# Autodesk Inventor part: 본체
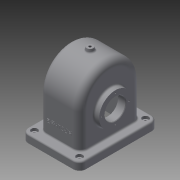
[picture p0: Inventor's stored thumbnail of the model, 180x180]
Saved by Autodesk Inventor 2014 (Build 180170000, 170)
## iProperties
Created: 2016-10
Part Number: 본체
Material: 일반
Document SubType Name: Modeling
Designer: USER
Density: 1 g/cm^3
Appearance: 기본값
Author: USER
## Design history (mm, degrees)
sketch "스케치1"
  geometry: L1 (-58, -65)-(-58, 0); L2 (58, 0)-(58, -65); L3 (58, -65)-(-58, -65); A1 r 58 centre (0, 0) between (58, 0) and (-58, 0); 1 further point
  constraints: 6 end point, 2 point on circle, 2 tangent, 1 centre point, 1 coincident, 1 parallel, 1 perpendicular, 1 vertical
  dimensions: "d0" = 65 distance from line of L3 point (0, 0); "d1" = 58 radius of A1; "d2" = 123 dimension on A1 L3
extrude "돌출1" new body sketch "스케치1" stored distance "d3" = 77; taper "d4" = 0 deg
node "작업 평면1"
sketch "스케치2"
  geometry: L1 (55, -75)-(-55, -75); L2 (-55, -75)-(-55, 75); L3 (-55, 75)-(55, 75); L4 (55, 75)-(55, -75); L5 (55, -75)-(-55, 75); L6 (-55, -75)-(55, 75); 1 further point
  constraints: 12 end point, 2 midpoint, 2 parallel, 1 horizontal, 1 perpendicular
  dimensions: "d6" = 110 distance of L2.end L3.end; "d7" = 150 distance of L1.end L2.end
extrude "돌출2" join sketch "스케치2" distance "d8" = 15; taper "d9" = 0 deg
sketch "스케치3"
  geometry: L1 (-58, -65)-(-58, 0) reference; L2 (-58, -65)-(-58, 0) reference; L3 (58, 0)-(58, -65) reference; L4 (58, -65)-(-58, -65) reference; L5 (52, -80)-(52, 0); L6 (-52, 0)-(-52, -80); L7 (-75, -80)-(75, -80) reference; L8 (-75, -80)-(-75, -65) reference; L9 (75, -65)-(-75, -65) reference; L10 (75, -80)-(75, -65) reference; A1 r 58 centre (0, 0) between (58, 0) and (-58, 0) reference; A2 r 58 centre (0, 0) between (58, 0) and (-58, 0) reference; A3 r 52 centre (0, 0) between (52, 0) and (-52, 0); 1 further point
  constraints: 4 end point, 2 point on circle, 2 point on line, 1 centre point
  dimensions: "d10" = 6 radial gap between concentric circles of A1 A3; "d11" = 6 distance between parallel lines of L1 L6; "d12" = 6 distance between parallel lines of L3 L5
extrude "돌출3" cut sketch "스케치3" stored distance "d13" = 67; taper "d14" = 0 deg
sketch "스케치4"
  geometry: L1 (80, 75)-(80, -75) reference; C1 r 31 at (15, 0); 1 further point
  constraints: 1 centre point, 1 horizontal alignment
  dimensions: "d15" = 62 diameter of C1; "d16" = 65 distance from line of L1 C1.centre
extrude "돌출4" join sketch "스케치4" distance "d17" = 10; taper "d18" = 0 deg
sketch "스케치5"
  geometry: L1 (-80, -75)-(-80, 75) reference; C1 r 37.5 at (-15, 0); 1 further point
  constraints: 1 centre point, 1 horizontal alignment
  dimensions: "d19" = 75 diameter of C1; "d20" = 65 distance from line of L1 C1.centre
extrude "돌출5" join sketch "스케치5" distance "d21" = 5; taper "d22" = 0 deg
hole "구멍1" diameter "d25" = 40; stored, may be unused: countersink angle "d29" = 90 deg, drill point angle "d31" = 118 deg; dims "d26" = 6, "d27" = 4, "d28" = 2, "d30" = 8, "d37" = 10, "d38" = 10
sketch "스케치6"
  geometry: L1 (33.5, -35)-(33.5, 5) reference; L2 (33.5, 24.747)-(33.5, -15); L3 (33.5, -15)-(19.5, -15); L4 (19.5, -15)-(19.5, 13); L5 (19.5, 13)-(33.5, 24.747); L6 (-33.5, -80)-(33.5, -80) reference; 1 further point
  constraints: 8 end point, 2 collinear, 1 parallel, 1 perpendicular
  dimensions: "d32" = 50 deg angle of L4 L5; "d33" = 14 distance between parallel lines of L4 L1; "d34" = 56 diameter of L4.end L3; "d35" = 65 distance between parallel lines of L6 L3
revolve "회전1" sketch "스케치6" stored, may be unused: angle "d36" = 90 deg
hole "구멍2" diameter "d41" = 40; stored, may be unused: countersink angle "d45" = 90 deg, drill point angle "d47" = 118 deg; dims "d39" = 10, "d40" = 10, "d42" = 6, "d43" = 4, "d44" = 2, "d46" = 8
node "작업 평면2"
sketch "스케치7"
  geometry: L1 (-38.5, 58)-(-38.5, -58) reference; C1 r 6 at (0, 0); 1 further point
  constraints: 1 centre point, 1 coincident
  dimensions: "d49" = 12 diameter of C1; "d50" = 38.5 distance from line of C1.centre L1
extrude "돌출6" join sketch "스케치7" stored distance "d51" = 5; taper "d52" = 10 deg
sketch "스케치8"
  geometry: C1 r 20 at (0, 0) reference; 2 further points
  constraints: 1 vertical alignment
  dimensions: "d53" = 26 distance of C1.centre point (0, 26)
hole "구멍3" sketch "스케치8" at (0, 26) diameter "d54" = 2.459; stored, may be unused: countersink angle "d58" = 90 deg, drill point angle "d60" = 118 deg; dims "d55" = 6, "d56" = 4, "d57" = 2, "d59" = 8
sketch "스케치9"
  geometry: C1 r 20 at (0, 0) reference; 2 further points
  constraints: 1 vertical alignment
  dimensions: "d64" = 29 distance of C1.centre point (0, 29)
hole "구멍4" sketch "스케치9" at (0, 29) diameter "d65" = 2.459; stored, may be unused: countersink angle "d69" = 90 deg, drill point angle "d71" = 118 deg; dims "d66" = 6, "d67" = 4, "d68" = 2, "d70" = 8
hole "구멍5" diameter "d77" = 4.459; stored, may be unused: countersink angle "d81" = 90 deg, drill point angle "d83" = 118 deg; dims "d75" = 10, "d76" = 10, "d78" = 6, "d79" = 4, "d80" = 2, "d82" = 8
chamfer "모따기1" distance "d84" = 1; stored, may be unused: second distance "d85" = 2, angle "d86" = 45 deg
fillet "모깎기1" dims "d87" = 3
fillet "모깎기2" dims "d88" = 13
fillet "모깎기3" dims "d89" = 3
fillet "모깎기4" dims "d90" = 8
fillet "모깎기5" dims "d91" = 12
fillet "모깎기6" dims "d92" = 3
sketch "스케치10"
  geometry: A1 r 9 centre (-43, 63) between (-43, 72) and (-52, 63) reference; 2 further points
  constraints: 1 coincident
hole "구멍6" sketch "스케치10" at (-43, 63) diameter "d93" = 5; stored, may be unused: countersink angle "d97" = 90 deg, drill point angle "d99" = 118 deg; dims "d94" = 6, "d95" = 12, "d96" = 5, "d98" = 8
fillet "모깎기7" dims "d100" = 3
node "작업 평면3"
sketch "스케치11"
  geometry: L1 (43, -80)-(-43, -80) reference; L2 (-38.5, 0)-(-38.5, -62) reference; 2 further points
  constraints: 1 other
  dimensions: "d102" = 40 distance from line of point (0, -40) L1; "d103" = 38.5 distance from line of point (0, -40) L2
feature "엠보싱1" sketch "스케치11" dims "d104" = 0.5, "d105" = 0
node "솔리드1"
pattern_circular "원형 패턴1" dims angle "d62" = 360 deg
pattern_circular "원형 패턴2" dims angle "d73" = 360 deg
mirror "대칭1"
mirror "대칭2"
node "투영된 루프1"
node "투영된 루프2"
other parameters: "d48" = 144
